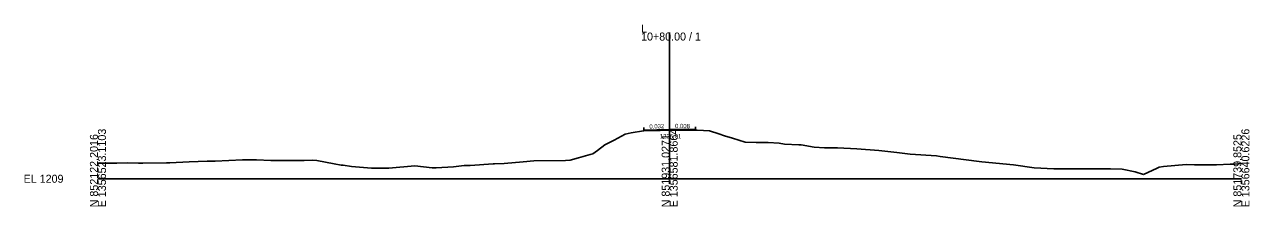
# Model space of a CAD drawing. Extents: x -26 to 4603, y -10 to 4066.
# Drawn here: x -25.7 to 402.8, y -9.7 to 53.9 of the extents above; entities that cross this region are included whole.
import ezdxf

# ---------------------------------------------------------------- set-up
doc = ezdxf.new("R2010")
doc.units = 0
for name, color, linetype in [('Exist Cross Section Cell', 7, 'Continuous'), ('Exist XS Center Line Elevation Label', 7, 'Continuous'), ('Exist XS Ground Line', 7, 'Continuous'), ('Prop XS Dump Level', 7, 'Continuous'), ('Prop XS EOT Tick Mark', 7, 'Continuous'), ('Prop XS Finish Grade', 7, 'Continuous'), ('Prop XS Finish Grade Pavement', 7, 'Continuous'), ('Prop XS SE Text', 7, 'Continuous'), ('Prop XS Wedging', 7, 'Continuous')]:
    doc.layers.add(name, color=color, linetype=linetype)

msp = doc.modelspace()

# ---------------------------------------------------------------- linework, layer by layer
at = {"layer": 'Exist Cross Section Cell'}
for p, q in [((200, 0), (200, 51.09)), ((0, 0), (200, 0)), ((200, 0), (400, 0))]:
    msp.add_line(p, q, dxfattribs=at)
at = {"layer": 'Exist XS Ground Line'}
for p, q in [((177.34, 11.79), (180.54, 13.45)), ((180.54, 13.45), (184.42, 15.55)), ((184.42, 15.55), (186.5, 16.08)), ((186.5, 16.08), (190.84, 16.73)), ((190.84, 16.73), (196.63, 16.9)), ((196.63, 16.9), (200, 17.01)), ((200, 17.01), (200.61, 17.03)), ((200.61, 17.03), (204.69, 17)), ((204.69, 17), (209.58, 16.95)), ((209.58, 16.95), (211.8, 16.87)), ((211.8, 16.87), (213.91, 16.72)), ((213.91, 16.72), (217.16, 15.74)), ((217.16, 15.74), (219.24, 15.04)), ((219.24, 15.04), (221.99, 14.22)), ((221.99, 14.22), (226.41, 12.81)), ((172.23, 8.48), (173.16, 8.68)), ((173.16, 8.68), (174.71, 9.86)), ((174.71, 9.86), (177.34, 11.79)), ((226.41, 12.81), (230.21, 12.64)), ((230.21, 12.64), (233, 12.68)), ((233, 12.68), (234.42, 12.7)), ((234.42, 12.7), (238.29, 12.42)), ((238.29, 12.42), (240.21, 12.12)), ((240.21, 12.12), (245.2, 11.9)), ((245.2, 11.9), (245.98, 11.86)), ((245.98, 11.86), (250.53, 11.02)), ((250.53, 11.02), (254.16, 10.83)), ((254.16, 10.83), (258.68, 10.85)), ((258.68, 10.85), (265.5, 10.44)), ((265.5, 10.44), (273.21, 9.86)), ((273.21, 9.86), (279.48, 9.11)), ((279.48, 9.11), (284.16, 8.62)), ((284.16, 8.62), (293.4, 7.95)), ((0, 5.39), (0.44, 5.39)), ((0.44, 5.39), (6.56, 5.42)), ((6.56, 5.42), (10.46, 5.52)), ((10.46, 5.52), (14.15, 5.4)), ((14.15, 5.4), (15.03, 5.41)), ((15.03, 5.41), (15.69, 5.43)), ((15.69, 5.43), (23.96, 5.55)), ((23.96, 5.55), (25.17, 5.59)), ((25.17, 5.59), (31.89, 5.89)), ((31.89, 5.89), (38.17, 6.12)), ((38.17, 6.12), (40.98, 6.16)), ((40.98, 6.16), (50.52, 6.57)), ((50.52, 6.57), (54.12, 6.66)), ((54.12, 6.66), (55.46, 6.66)), ((55.46, 6.66), (60.43, 6.41)), ((60.43, 6.41), (66.59, 6.39)), ((66.59, 6.39), (72.12, 6.4)), ((72.12, 6.4), (74.94, 6.51)), ((74.94, 6.51), (76.62, 6.42)), ((76.62, 6.42), (82.6, 5.23)), ((82.6, 5.23), (85.11, 4.79)), ((85.11, 4.79), (85.83, 4.75)), ((85.83, 4.75), (88.68, 4.32)), ((88.68, 4.32), (95.73, 3.72)), ((101.78, 3.64), (110.85, 4.49)), ((110.85, 4.49), (116.91, 3.79)), ((124.36, 4.13), (128.13, 4.68)), ((128.13, 4.68), (130.23, 4.67)), ((130.23, 4.67), (138.21, 5.23)), ((138.21, 5.23), (138.72, 5.23)), ((138.72, 5.23), (142.12, 5.34)), ((142.12, 5.34), (148.81, 5.9)), ((148.81, 5.9), (152.43, 6.22)), ((152.43, 6.22), (163.55, 6.43)), ((163.55, 6.43), (165.2, 6.46)), ((165.2, 6.46), (168.08, 7.28)), ((168.08, 7.28), (172.23, 8.48)), ((293.4, 7.95), (294.58, 7.8)), ((294.58, 7.8), (308.29, 6.03)), ((308.29, 6.03), (309.16, 5.92)), ((309.16, 5.92), (320.26, 4.86)), ((320.26, 4.86), (327.53, 3.85)), ((372.76, 4.22), (380.68, 4.92)), ((380.68, 4.92), (383.62, 4.91)), ((383.62, 4.91), (386.9, 4.89)), ((386.9, 4.89), (388.39, 4.91)), ((388.39, 4.91), (390.7, 4.88)), ((390.7, 4.88), (391.33, 4.89)), ((391.33, 4.89), (396.11, 5.05)), ((396.11, 5.05), (397.76, 5.12)), ((397.76, 5.12), (400, 5.31)), ((95.73, 3.72), (97.94, 3.66)), ((97.94, 3.66), (98.7, 3.66)), ((98.7, 3.66), (101.78, 3.64)), ((116.91, 3.79), (118.3, 3.86)), ((118.3, 3.86), (124.36, 4.13)), ((327.53, 3.85), (334.42, 3.51)), ((334.42, 3.51), (337.67, 3.43)), ((337.67, 3.43), (350.93, 3.43)), ((350.93, 3.43), (354.24, 3.42)), ((354.24, 3.42), (358.34, 3.4)), ((358.34, 3.4), (362.82, 2.36)), ((362.82, 2.36), (365.75, 1.46)), ((365.75, 1.46), (370.53, 3.64)), ((370.53, 3.64), (371.29, 4.02)), ((371.29, 4.02), (372.76, 4.22))]:
    msp.add_line(p, q, dxfattribs=at)
at = {"layer": 'Prop XS Dump Level'}
for p, q in [((200, 17.22), (191, 16.93)), ((209, 17.15), (200, 17.22))]:
    msp.add_line(p, q, dxfattribs=at)
at = {"layer": 'Prop XS EOT Tick Mark'}
for p, q in [((191, 16.93), (191, 17.93)), ((209, 17.15), (209, 18.15))]:
    msp.add_line(p, q, dxfattribs=at)
at = {"layer": 'Prop XS Finish Grade'}
msp.add_line((209, 17.15), (209, 16.96), dxfattribs=at)
at = {"layer": 'Prop XS Finish Grade Pavement'}
for p, q in [((191, 16.93), (200, 17.22)), ((200, 17.22), (209, 17.15))]:
    msp.add_line(p, q, dxfattribs=at)
at = {"layer": 'Prop XS Wedging'}
msp.add_lwpolyline([(191, 16.73), (191, 16.85), (196.63, 17.03), (200, 17.14), (200.61, 17.13), (204.69, 17.1), (209, 17.07), (209, 16.96), (204.69, 17), (200.61, 17.03), (200, 17.01), (196.63, 16.9)], close=True, dxfattribs=at)

# ---------------------------------------------------------------- texts
at = {"layer": 'Exist Cross Section Cell'}
for s, p in [('L', (190, 51.09)), ('10+80.00 / 1', (190, 48.29)), ('EL 1209', (-26, -1.4))]:
    msp.add_text(s, height=2.8, dxfattribs=at).set_placement(p)
for s, p in [('E 1356523.1103', (2.8, -10)), ('E 1356581.8664', (202.8, -10)), ('E 1356640.6226', (402.8, -10)), ('N 852122.2016', (0, -10)), ('N 851931.0271', (200, -10)), ('N 851739.8525', (400, -10))]:
    msp.add_text(s, height=2.8, rotation=90, dxfattribs=at).set_placement(p)
at = {"layer": 'Exist XS Center Line Elevation Label'}
msp.add_text('1226.01', height=1.5, dxfattribs=at).set_placement((196.56, 14.1))
at = {"layer": 'Prop XS SE Text'}
for s, rotation, p in [('0.032', 1.8086, (192.93, 17.5)), ('0.008', 359.5416, (201.89, 17.7))]:
    msp.add_text(s, height=1.5, rotation=rotation, dxfattribs=at).set_placement(p)

doc.saveas('drawing.dxf')
